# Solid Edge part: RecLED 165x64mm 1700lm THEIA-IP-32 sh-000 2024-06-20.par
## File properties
Author: robert.pupel
Template: iso metric part.par
Last saved by: robert.pupel
Revision: 1
Application: Solid Edge
Gęstość: 0.000 kg/m^3
Dokładność: 0.990
Username: robert.pupel
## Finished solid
Body 1: solid body, 958 faces, 2518 edges, 1678 vertices.
  Faces by surface: plane 836, cylinder 96, swept 14, cone 6, sphere 4, spline 2
  Edges by curve: line 2200, curve on surface 100, circle 98, ellipse 72, spline 48
Bounding box of the edges (mm; curved faces can reach further): 63.400 x 4.230 x 165.000, from (-32.4, -2.73, -82.5) to (31, 1.5, 82.5).
Cylindrical faces by radius (mm): R0.0495 x2, R0.0647 x4, R0.0649 x4, R0.1 x4, R0.1164 x2, R0.1314 x8, R0.1729 x2, R0.2289 x2, R0.47 x4, R0.5 x28, R0.6 x2, R0.625 x2, R0.75 x4, R1.0277 x2, R1.05 x2, R1.3 x2, R1.5309 x2, R1.5312 x2, R1.7414 x2, R1.7423 x2, R2.25 x2, R3.2 x2, R5 x2, R7.15 x8
Conical faces (half-angle, radius in mm at the cone's reference point): 36.872 deg R0.8536 x2, 45 deg R3.2 x4
Spherical faces by radius (mm): R0.5 x4
Planar faces by outward normal: +x 78, +y 7, +z 71, -x 78, -y 115, -z 103, oblique 384
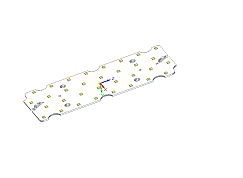
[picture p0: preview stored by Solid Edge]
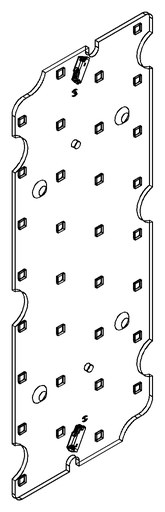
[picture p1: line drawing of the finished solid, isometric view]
